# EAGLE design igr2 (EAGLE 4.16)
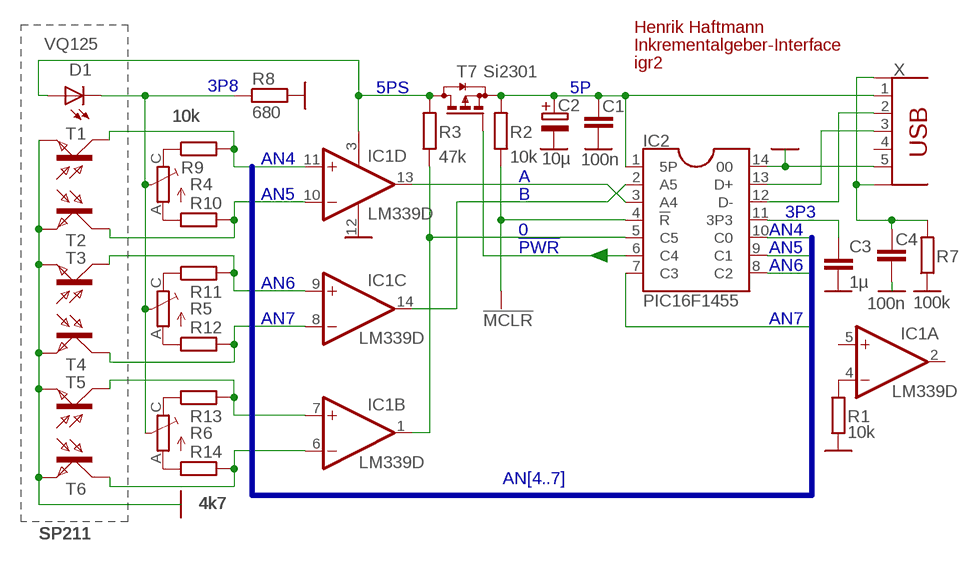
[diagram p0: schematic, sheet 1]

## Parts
!MCLR  PADS  [SMD-1MM]
C1  100n  C0603  [0603@1]
C2  10µ  E01-5  [E01-5]
C3  1µ  C0603  [0603@1]
C4  100n  C0603  [0603@1]
D1  VQ125  LED0603  [0603]
IC1  LM339D  [SO14]
IC2  PIC16F1455  PIC16F1455-I/SL  [SO14]
R1  10k  R0603  [0603@1]
R2  10k  R0603  [0603@1]
R3  47k  R0603  [0603@1]
R4  10k  RTRIM  [RTRIM-RFT]
R5  10k  RTRIM  [RTRIM-RFT]
R6  10k  RTRIM  [RTRIM-RFT]
R7  100k  R0603  [0603@1]
R8  680  R0603  [0603@1]
R9  4k7  R0603  [0603@1]
R10  4k7  R0603  [0603@1]
R11  4k7  R0603  [0603@1]
R12  4k7  R0603  [0603@1]
R13  4k7  R0603  [0603@1]
R14  4k7  R0603  [0603@1]
T1  SP211  BPX81  [BPX81]
T2  SP211  BPX81  [BPX81]
T3  SP211  BPX81  [BPX81]
T4  SP211  BPX81  [BPX81]
T5  SP211  BPX81  [BPX81]
T6  SP211  BPX81  [BPX81]
T7  Si2301  PMOS  [SOT23]
X  USB5+2MINI  [USB-MINIB]

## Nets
0: IC1.1(B:OUT) IC2.5(C5) R3.1
3P3: C3.1 IC2.11(3P3)
3P8: D1.2(K) R4.B(S) R5.B(S) R6.B(S) R8.1
5P: C1.1 C2.+ IC2.1(5P) R2.2 T7.2(S) X.1
5PS: D1.1(A) IC1.3(P:V+) R3.2 T7.3(D)
!PWR: IC2.6(C4) T7.1(G)
A: IC1.13(D:OUT) IC2.3(A4)
AN4: IC1.11(D:+IN) IC2.10(C0) R9.2 T1.C
AN5: IC1.10(D:-IN) IC2.9(C1) R10.2 T2.C
AN6: IC1.9(C:+IN) IC2.8(C2) R11.2 T3.C
AN7: IC1.8(C:-IN) IC2.7(C3) R12.2 T4.C
B: IC1.14(C:OUT) IC2.2(A5)
D+: IC2.13(D+) X.3
D-: IC2.12(D-) X.2
GND: C1.2 C2.- C3.2 C4.2 IC1.12(P:GND) IC2.14 R1.2 R7.1 R8.2 T1.E T2.E T3.E T4.E T5.E T6.E X.5
N$1: R4.C(E) R9.1
N$2: R4.A R10.1
N$3: R5.C(E) R11.1
N$4: R5.A R12.1
N$5: IC1.4(A:-IN) R1.1
N$6: R6.C(E) R13.1
N$7: R6.A R14.1
N$10: IC1.7(B:+IN) R13.2 T5.C
N$11: IC1.6(B:-IN) R14.2 T6.C
N$26: !MCLR.1 IC2.4(!R) R2.1
PE: C4.1 R7.2 X.M1(S) X.M2(S)
Unconnected: IC1.2(A:OUT) IC1.5(A:+IN) X.4

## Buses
AN[4..7]

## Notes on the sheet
- Henrik Haftmann
- Inkrementalgeber-Interface

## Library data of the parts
!MCLR = fu:PAD: Anschlussfeld
C1 C3 C4 = fu:C: Kondensator
C2 = fu:E: Elektrolytkondensator, gepolt
D1 = fu:LED: Leuchtdiode
IC1 = linear:LM339: Low Power Low Offset Voltage Quad Comparators with open collector; LM139/LM239/LM339/LM2901/LM3302
IC2 = hs-ul:PIC16F145*: 8-bit-Mikrocontroller mit USB Gezeichnet in Gehäuse-Anordnung, für USB-PCS500-Adapter. Typen: PIC16F1454 PIC16F1455 (mit ADU, DAU und 2x Analogvergleicher) Jeweils 8K x 14bit Flash, 1K RAM Features Benötigt keinen Quarz, interne PLL Benötigt keine USB-Serienwiderstände 3,3-V-Spannungsregler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
R1-R3 R7-R14 = fu:R: Widerstand
R4-R6 = us1:RTRIM: Einstell-Potenziometer
T1-T6 = opto-trans-siemens:BPX81: PHOTO TRANSISTOR
T7 = w:PMOS: p-Kanal-MOSFET
X = w:USB5+2: USB-Buchse (A oder B) Standardausführung der USB-Version 1.0, 4-polig Mit 2 Schirmanschlüssen

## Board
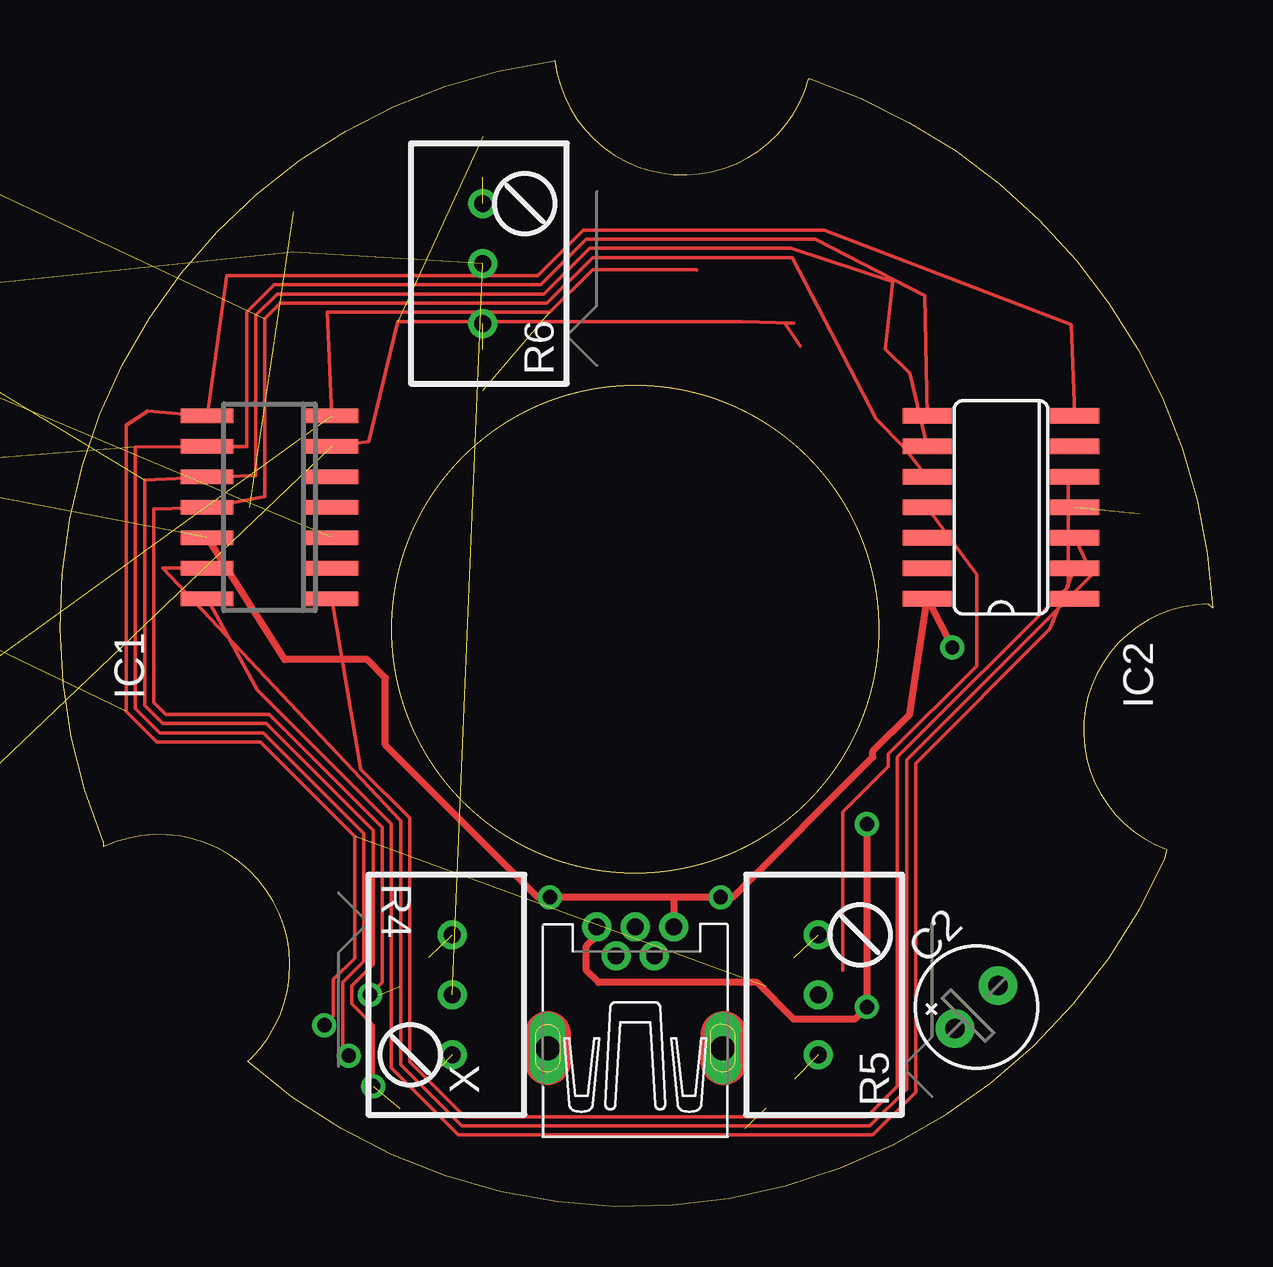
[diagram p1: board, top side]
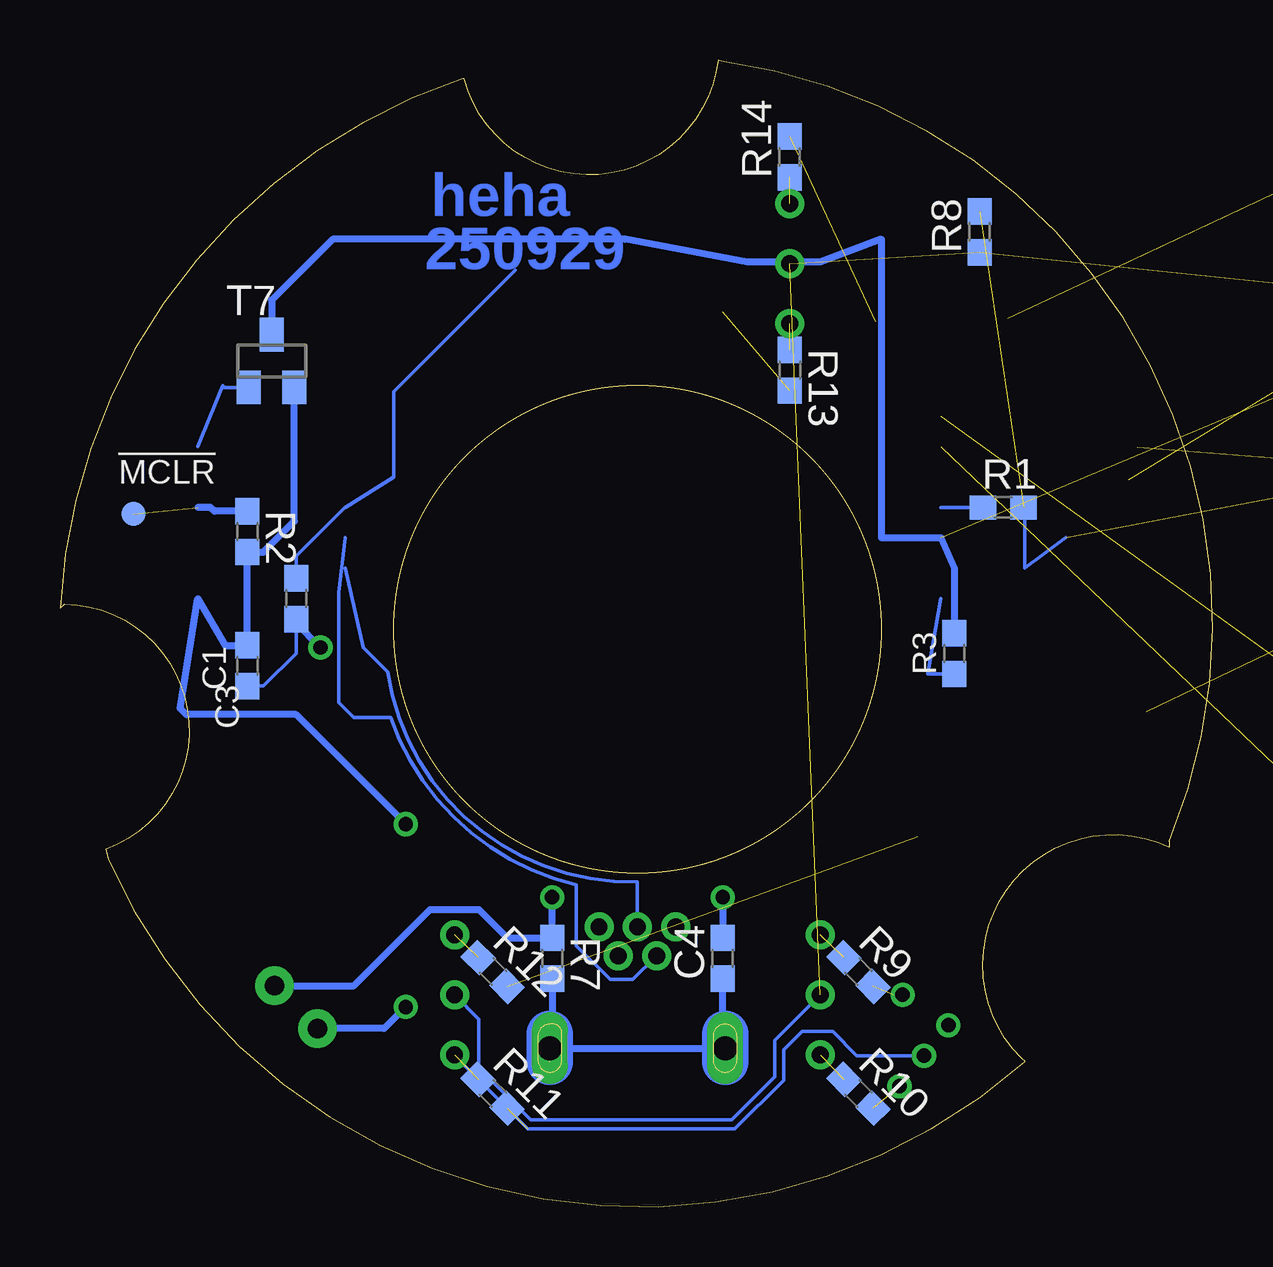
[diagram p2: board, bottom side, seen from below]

Size 48.03 x 47.79 mm. Coordinates in mm from the lower left corner, seen from the top.
Outline: 1.81,15.23 arc-105 20.48,47.75 20.61,47.79 arc158 31.19,47 31.25,47.01 arc-69 48.03,24.96 47.84,25.11 arc159 46.12,14.89 46.02,14.49 arc-108 7.81,6.05 7.96,6.18 arc161 1.81,14.99 1.81,15.23
Outline: circle at 23.97,24.07 radius 10.16
Copper layers (1*16): Top 0.035mm / dielectric 1.5mm / Bottom 0.035mm
Design rules "default": minimum track width 0.15mm, minimum drill 0.3mm, track to track 0.15mm, track to pad 0.15mm, pad to pad 0.15mm, via to via 0.15mm, smd to smd 0mil, copper to edge 0.3mm, drill to drill 0.3mm, minimum pad ring 10mil, minimum via ring 8mil, stop-mask expansion 4mil, vias tented up to drill 0mil, thermal gap 10mil
bRestrict: area 39.5,14.5 to 44.6,19.6; area 7.6,7.7 to 13.2,13.3; area 17.9,40 to 25.5,47.6

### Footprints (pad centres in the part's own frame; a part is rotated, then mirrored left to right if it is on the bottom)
SMD-1MM = smd 1 x 1: 1 0,0
0603@1 = smd 1.1 x 1: 1 -0.85,0; 2 0.85,0
E01-5 = drill 0.813 pad 1.6 round: + -1.27,0; - 1.27,0
0603 = smd 1.1 x 1: 1 -0.85,0; 2 0.85,0
SO14 = smd 0.6 x 2.2: 1 -3.81,-2.6; 2 -2.54,-2.6; 3 -1.27,-2.6; 4 0,-2.6; 5 1.27,-2.6; 6 2.54,-2.6; 7 3.81,-2.6; 8 3.81,2.6; 9 2.54,2.6; 10 1.27,2.6; 11 0,2.6; 12 -1.27,2.6; 13 -2.54,2.6; 14 -3.81,2.6
SO14' = smd 0.66 x 2.032: 1 -3.81,-3.073; 2 -2.54,-3.073; 3 -1.27,-3.073; 4 0,-3.073; 5 1.27,-3.073; 6 2.54,-3.073; 7 3.81,-3.073; 8 3.81,3.073; 9 2.54,3.073; 10 1.27,3.073; 11 0,3.073; 12 -1.27,3.073; 13 -2.54,3.073; 14 -3.81,3.073
RTRIM-RFT = drill 0.7 round: A 2.5,0; B 0,0; C -2.5,0
BPX81 = drill 0.813 long: C 1.27,0; E -1.27,0
SOT23 = smd 1 x 1.4: 1 -0.95,-1.1; 2 0.95,-1.1; 3 0,1.1
USB-MINIB = drill 0.7 pad 1.016 round: 1 2.825,1.6; 2 1.625,0.8; 3 2.825,0; 4 1.625,-0.8; 5 2.825,-1.6 | drill 1 pad 1.422 long: M1 -2.225,3.65; M2 -2.225,-3.65

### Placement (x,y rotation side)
!MCLR  44.97,28.87 0 bottom
C1  40.22,22.54 270 bottom
C2  38.19,8.32 45 top
C3  38.19,25.34 270 bottom
C4  20.41,10.35 90 bottom
D1  not placed on the board
IC1  8.73,29.15 90 top
IC2  PIC16F1455  [SO14']  39.21,29.15 90 top
R1  8.73,29.15 0 bottom
R2  40.22,28.13 270 bottom
R3  10.76,23.05 90 bottom
R4  16.35,8.83 270 top
R5  31.59,8.83 90 top
R6  17.62,39.31 90 top
R7  27.52,10.35 270 bottom
R8  9.71,40.63 90 bottom
R9  14.76,9.78 315 bottom
R10  14.76,4.7 315 bottom
R11  30,4.7 315 bottom
R12  30,9.78 315 bottom
R13  17.62,34.86 270 bottom
R14  17.62,43.75 90 bottom
T1  not placed on the board
T2  not placed on the board
T3  not placed on the board
T4  not placed on the board
T5  not placed on the board
T6  not placed on the board
T7  39.21,35.24 0 bottom
X  23.97,8.83 90 top

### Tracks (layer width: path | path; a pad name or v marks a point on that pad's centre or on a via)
0  (1 unrouted)
  Top 0.15: IC1.1 12.54,18.23 14.57,16.19 14.57,6.03 16.86,3.75 33.62,3.75 34.89,5.02 34.89,18.73 42,25.85 42,30.67 IC2.5
  Bottom 0.15: R3.1 11.86,22.2 IC1.1
3P3  (1 unrouted)
  Top 0.15: 32.6,9.84 32.6,16.45 34.51,18.35 34.51,18.86 38.19,22.54 38.19,26.35 IC2.11
  Bottom 0.15: C3.1 38.19,27.12 36.16,29.15 IC2.11 34.13,30.42 34.13,33.97 29.06,39.04
3P8  (3 unrouted)
  Bottom 0.15: R4.B 18.25,6.92 18.25,5.4 20.03,3.62 28.41,3.62 30.57,5.78 30.57,7.81 R5.B
5P  (via drill 0.6)  (1 unrouted)
  Top 0.3: X.1 22.37,11.29 21.94,10.86 21.94,9.84 22.44,9.34 29.05,9.34 30.57,7.81 33.11,7.81 v33.62,8.32 v33.62,15.94
  Bottom 0.3: C2.+ 34.52,7.42 v33.62,8.32 | v33.62,15.94 38.19,20.51 42.76,20.51 43.02,20.77 IC2.1 41.15,23.39 C1.1 R2.2 39.55,27.28 38.26,28.57 T7.2
5PS  (2 unrouted)
  Bottom 0.3: T7.3 39.21,37.78 36.67,40.32 24.48,40.32 19.4,39.37 16.35,39.37 13.81,40.32 13.81,27.88 IC1.3 10.76,26.61 R3.2
!PWR  (1 unrouted)
  Bottom 0.15: T7.1 41.16,34.14 41.24,34.23 IC2.6
A
  Top 0.15: IC1.13 4.28,26.61 14.19,16.07 14.19,5.91 16.73,3.37 33.75,3.37 35.27,4.89 35.27,18.61 43.02,26.35 IC2.3
AN4  (via drill 0.6)  (2 unrouted)
  Top 0.15: v12.92,8.83 13.43,9.34 13.43,15.81 8.73,20.51 4.41,20.51 3.9,21.02 3.9,29.08 IC1.11 8.54,29.59 8.54,37.02 9.17,37.66 20.29,37.66 22.19,39.56 30.51,39.56 34,32.83 35.14,31.69 IC2.10
  Bottom 0.15: v12.92,8.83 13.3,8.83
AN5  (via drill 0.6)  (2 unrouted)
  Top 0.15: v13.05,5.02 13.05,7.56 12.16,8.45 12.16,9.21 13.05,10.1 13.05,15.69 8.6,20.13 4.28,20.13 3.52,20.89 3.52,30.29 IC1.10 8.16,30.48 8.16,37.15 9.05,38.04 20.16,38.04 22.06,39.94 30.45,39.94 34.7,38.55 34.38,35.75 35.4,34.74 IC2.9
AN6  (via drill 0.6)  (2 unrouted)
  Top 0.15: v12.03,6.29 11.78,6.54 11.78,9.34 12.67,10.22 12.67,15.56 8.47,19.75 4.16,19.75 3.14,20.77 3.14,31.66 IC1.9 7.78,31.69 7.78,37.28 8.92,38.42 20.03,38.42 21.94,40.32 31.46,40.32 36.03,37.97 IC2.8
  Bottom 0.15: v12.03,6.29 14.82,6.29 15.84,7.3 17.11,7.3 17.87,6.54 17.87,5.27 19.9,3.24 28.54,3.24 31.59,6.29
AN7  (via drill 0.6)  (2 unrouted)
  Top 0.15: v11.01,7.56 11.4,7.94 11.4,9.46 12.28,10.35 12.28,15.43 8.35,19.37 4.03,19.37 2.76,20.64 2.76,32.58 3.65,33.15 IC1.8 6.95,38.8 19.9,38.8 21.81,40.7 31.84,40.7 42.13,36.77 IC2.7
B
  Top 0.15: IC1.14 8.22,21.53 13.81,15.94 13.81,5.78 16.6,2.99 33.87,2.99 35.65,4.76 35.65,18.48 41.24,24.07 IC2.2
D+  (1 unrouted)
  Bottom 0.15: X.3 23.97,13.53 arc83 34.38,22.29 35.4,23.31 IC2.13
D-  (1 unrouted)
  Bottom 0.15: IC2.12 36.41,25.59 36.41,21.02 35.78,20.38 34.26,20.38 arc-57 26.51,13.4 26.51,10.86 25.11,9.46 24.16,9.46 X.2
GND  (via drill 0.6)  (8 unrouted)
  Top 0.3: X.5 25.57,12.82 25.49,12.89 | 25.49,12.89 v20.41,12.89 19.9,12.89 13.55,19.24 13.55,22.04 12.79,22.8 9.36,22.8 IC1.12 | 25.49,12.89 v27.52,12.89 28.03,12.89 33.87,18.73 33.87,18.99 35.4,20.51 IC2.14 v37.18,23.31
  Bottom 0.15: C3.2 38.19,23.05 39.55,21.69 C1.2 | R1.2 7.84,29.15 7.84,26.61 IC1.12
  Bottom 0.3: v20.41,12.89 C4.2 | v27.52,12.89 R7.1 29.39,11.2 30.57,12.38 32.6,12.38 35.78,9.21 C2.- | C2.- | C3.2 38.19,24.32 v37.18,23.31
N$1  (1 unrouted)
N$2  (1 unrouted)
N$3  (1 unrouted)
N$4  (1 unrouted)
N$5  (1 unrouted)
  Bottom 0.15: IC1.4 R1.1
N$6  (1 unrouted)
N$7  (1 unrouted)
N$10  (2 unrouted)
  Top 0.15: IC1.7 11.14,37.28 20.41,37.28 22.19,39.05 26.51,39.05 26.52,39.04
N$11  (2 unrouted)
  Top 0.15: IC1.6 12.86,31.88 14.06,36.89 28.41,36.89 30.57,36.83 30.19,36.83 30.84,35.86
N$26  (2 unrouted)
  Bottom 0.3: R2.1 41.58,28.98 41.75,29.15 IC2.4
PE  (1 unrouted)
  Top 1.93: 20.32,7.18 X.M1 20.32,6.03 | 27.65,7.18 27.65,6.03
  Bottom 0.3: 20.32,7.21 20.41,7.3 C4.1 | 27.62,7.21 27.52,7.3 R7.2 | X.M2 X.M1
  Bottom 1.93: 20.32,7.21 X.M1 20.32,6.03 | 27.62,7.21 X.M2 27.62,6.03

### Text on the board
Bottom: heha | 250929
Measures: 5° | Teilkreis R24,5 | 10° | 35°
Document: bRestrict noch nicht vermessen!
